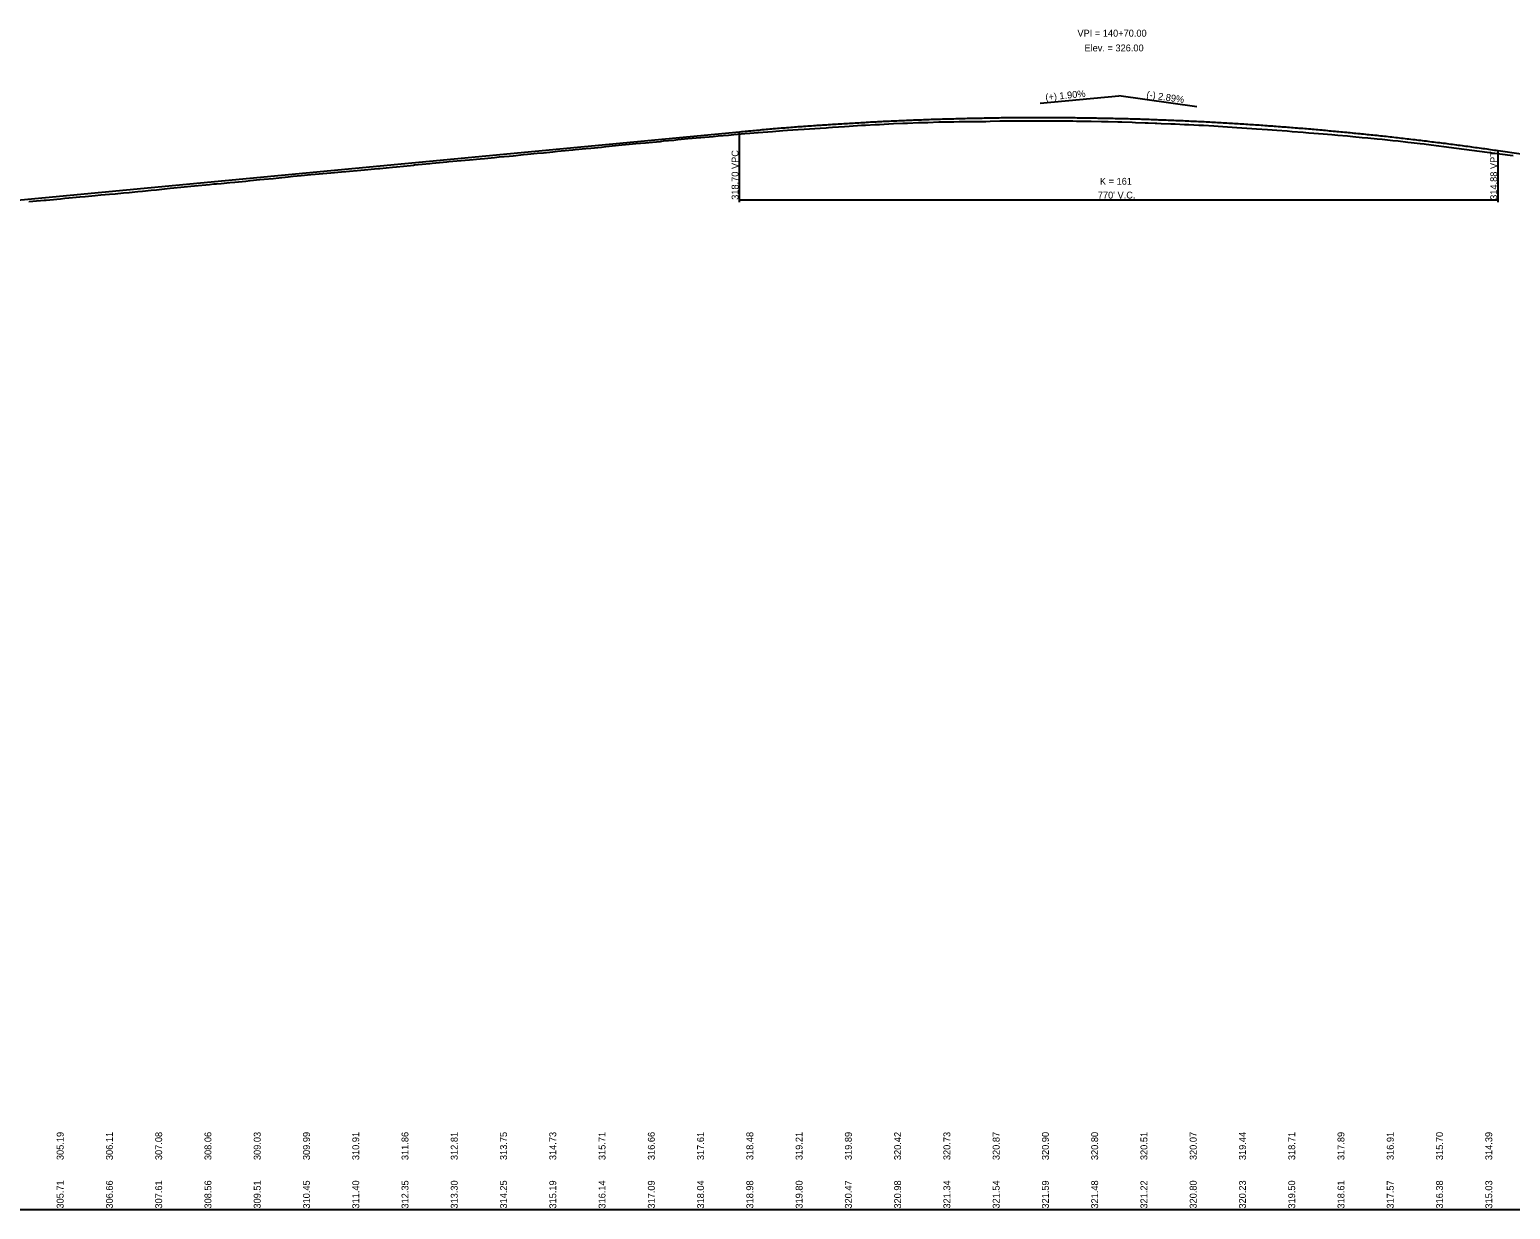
# Model space of a CAD drawing. Extents: x 1876258 to 1926563, y 729739 to 834437.
# Drawn here: x 1891328 to 1892831, y 827963 to 829160 of the extents above; entities that cross this region are included whole.
import ezdxf

# ---------------------------------------------------------------- set-up
doc = ezdxf.new("R2010")
doc.units = 0
for name, color, linetype in [('RD_EX_BldgApp', 7, 'Continuous'), ('RD_EX_H2O_BlueLn', 7, 'Continuous'), ('RD_EX_RailRoad', 7, 'Continuous'), ('RD_HC_Data', 7, 'Continuous'), ('RD_HC_TX_Sta50', 7, 'Continuous'), ('RD_PD_ALT5_CL', 7, 'Continuous'), ('RD_PD_Final_Cl', 7, 'Continuous')]:
    doc.layers.add(name, color=color, linetype=linetype)

msp = doc.modelspace()

# ---------------------------------------------------------------- linework, layer by layer
at = {"layer": 'RD_EX_BldgApp'}
for points in [[(1891683, 829019), (1891695.9, 829020.4), (1891700.1, 829020.8), (1891714.2, 829022.2), (1891717.3, 829022.5), (1891718.2, 829022.6), (1891733.7, 829024.2), (1891736.2, 829024.4), (1891750.9, 829025.8), (1891753.2, 829026), (1891769.6, 829027.4), (1891774.1, 829027.9), (1891784.9, 829028.9), (1891789.2, 829029.3), (1891799.6, 829030.2), (1891804.1, 829030.7), (1891814.2, 829031.6), (1891818.5, 829032), (1891828.9, 829033.1), (1891832.8, 829033.5), (1891842.9, 829034.4), (1891849.1, 829035), (1891858.7, 829036), (1891863.5, 829036.5), (1891874.9, 829037.6), (1891879, 829038), (1891881.3, 829038.2), (1891892.2, 829039.2), (1891897.1, 829039.7), (1891908.1, 829040.8), (1891912.6, 829041.3), (1891922.4, 829042.3), (1891928.7, 829042.9), (1891936.2, 829043.6), (1891942.9, 829044.2), (1891952.6, 829045.2), (1891959.8, 829045.8), (1891967.8, 829046.5), (1891970.9, 829046.9), (1891981.3, 829047.9), (1891985.4, 829048.3), (1891995.5, 829049.3), (1891999.9, 829049.7), (1892004, 829050.1), (1892008.7, 829050.5), (1892021.5, 829051.5), (1892026.5, 829052), (1892036.8, 829052.9), (1892042.2, 829053.4), (1892053.6, 829054.4), (1892058.7, 829054.9), (1892067.1, 829055.6), (1892076.7, 829056.3), (1892081.7, 829056.7), (1892092.2, 829057.4), (1892096.9, 829057.8), (1892107.7, 829058.5), (1892113.6, 829058.9), (1892124.7, 829059.6), (1892129.9, 829060), (1892136.1, 829060.4), (1892138.4, 829060.5), (1892142.6, 829060.9), (1892154.8, 829061.7), (1892159.5, 829062), (1892171.8, 829062.8), (1892175.9, 829063), (1892185.7, 829063.6), (1892190.1, 829063.8), (1892199.8, 829064.3), (1892204.5, 829064.5), (1892214, 829064.9), (1892218.7, 829065.1), (1892229.9, 829065.5), (1892234.5, 829065.6), (1892239.4, 829065.8), (1892250.4, 829066.2), (1892255.5, 829066.3), (1892265.7, 829066.5), (1892270.9, 829066.6), (1892280.8, 829066.7), (1892286.1, 829066.8), (1892298, 829066.8), (1892302.4, 829066.9), (1892312.2, 829067.2), (1892314.3, 829067.2), (1892317.7, 829067.2), (1892326.1, 829067.3), (1892330.8, 829067.4), (1892339.6, 829067.3), (1892344.2, 829067.3), (1892353.6, 829067.4), (1892357.9, 829067.3), (1892368.1, 829067.2), (1892371.7, 829067.2), (1892375.8, 829067.2), (1892386.4, 829067.2), (1892390, 829067.1), (1892401.7, 829067), (1892405.1, 829066.9), (1892415.5, 829066.7)], [(1892415.5, 829066.7), (1892418.6, 829066.7), (1892422.2, 829066.6), (1892432.1, 829066.3), (1892436, 829066.2), (1892446.6, 829065.9), (1892450.2, 829065.8), (1892460, 829065.4), (1892463, 829065.3), (1892470.1, 829065.1), (1892471.8, 829065), (1892476, 829064.8), (1892485.9, 829064.4), (1892490.4, 829064.2), (1892499.7, 829063.8), (1892504.1, 829063.6), (1892514.4, 829063.1), (1892519, 829062.8), (1892529.5, 829062.2), (1892534, 829061.9), (1892543.3, 829061.3), (1892553, 829060.7), (1892558, 829060.4), (1892568, 829059.7), (1892572.7, 829059.4), (1892583.9, 829058.5), (1892588.7, 829058.2), (1892593.5, 829057.8), (1892603.9, 829057.1), (1892609, 829056.7), (1892620.3, 829055.8), (1892622.8, 829055.6), (1892626.1, 829055.3), (1892631.1, 829054.9), (1892640.4, 829054.1), (1892649.2, 829053.4), (1892655.5, 829052.9), (1892665.1, 829052.1), (1892670.6, 829051.6), (1892680.1, 829050.6), (1892685.9, 829050), (1892695.4, 829049.1), (1892700.4, 829048.6), (1892711.3, 829047.5), (1892716.8, 829046.9), (1892726.3, 829045.8), (1892729.8, 829045.5), (1892738.9, 829044.4), (1892742.9, 829043.9), (1892745.1, 829043.6), (1892775.8, 829039.6), (1892830.4, 829032.5), (1892833.4, 829032.1)], [(1891326.9, 828985.4), (1891330.8, 828985.7), (1891342.4, 828986.7), (1891344.4, 828986.9), (1891348.2, 828987.3), (1891358.8, 828988.3), (1891363.2, 828988.8), (1891367.3, 828989.1), (1891378.6, 828990.2), (1891384, 828990.6), (1891394, 828991.5), (1891399.9, 828992.1), (1891408.8, 828992.9), (1891414.3, 828993.4), (1891422.9, 828994.3), (1891428.8, 828994.8), (1891437.3, 828995.6), (1891442.1, 828996.1), (1891451.1, 828997), (1891456.3, 828997.5), (1891467.1, 828998.6), (1891470.2, 828998.9), (1891481.1, 829000), (1891484.3, 829000.3), (1891491.3, 829001), (1891494.9, 829001.3), (1891510, 829002.8), (1891514.7, 829003.3), (1891517.3, 829003.5), (1891522.1, 829003.9), (1891530.8, 829004.7), (1891536, 829005.2), (1891547.2, 829006.3), (1891551.6, 829006.8), (1891561.2, 829007.8), (1891565.6, 829008.2), (1891574.9, 829009), (1891580.6, 829009.5), (1891590.1, 829010.5), (1891595.2, 829011.1), (1891603.3, 829011.9), (1891613.1, 829012.8), (1891617.5, 829013.2), (1891629.3, 829014.3), (1891633.4, 829014.6), (1891644.2, 829015.6), (1891648.7, 829016.1), (1891663.9, 829017.4), (1891667.5, 829017.7), (1891677.5, 829018.6), (1891681, 829018.9), (1891683, 829019)]]:
    msp.add_lwpolyline(points, dxfattribs=at)
at = {"layer": 'RD_EX_H2O_BlueLn'}
for p, q in [((1892048.1, 828984.7), (1892048.1, 829056.3)), ((1892818.1, 828984.7), (1892818.1, 829037.2)), ((1892048.1, 828987.2), (1892818.1, 828987.2))]:
    msp.add_line(p, q, dxfattribs=at)
at = {"layer": 'RD_HC_TX_Sta50'}
for p in [(1892353.4, 829085.3), (1892512.3, 829081.4)]:
    msp.add_line(p, (1892433.1, 829092.8), dxfattribs=at)
at = {"layer": 'RD_PD_ALT5_CL'}
for p, q in [((1889808.1, 828844), (1892048.1, 829056.3)), ((1892818.1, 829037.2), (1894783.1, 828753.6))]:
    msp.add_line(p, q, dxfattribs=at)
msp.add_spline([(1892048.1, 829056.3), (1892063.5, 829057.7), (1892078.9, 829059.1), (1892094.3, 829060.4), (1892109.7, 829061.6), (1892125.1, 829062.7), (1892140.5, 829063.7), (1892155.9, 829064.7), (1892171.3, 829065.6), (1892186.7, 829066.5), (1892202.1, 829067.2), (1892217.5, 829067.9), (1892232.9, 829068.5), (1892248.3, 829069.1), (1892263.7, 829069.5), (1892279.1, 829069.9), (1892294.5, 829070.2), (1892309.9, 829070.5), (1892325.3, 829070.7), (1892340.7, 829070.7), (1892356.1, 829070.8), (1892371.5, 829070.7), (1892386.9, 829070.6), (1892402.3, 829070.4), (1892417.7, 829070.1), (1892433.1, 829069.8), (1892448.5, 829069.4), (1892463.9, 829068.9), (1892479.3, 829068.3), (1892494.7, 829067.7), (1892510.1, 829067), (1892525.5, 829066.2), (1892540.9, 829065.3), (1892556.3, 829064.4), (1892571.7, 829063.4), (1892587.1, 829062.3), (1892602.5, 829061.1), (1892617.9, 829059.9), (1892633.3, 829058.6), (1892648.7, 829057.2), (1892664.1, 829055.8), (1892679.5, 829054.2), (1892694.9, 829052.7), (1892710.3, 829051), (1892725.7, 829049.2), (1892741.1, 829047.4), (1892756.5, 829045.5), (1892771.9, 829043.6), (1892787.3, 829041.5), (1892802.7, 829039.4), (1892818.1, 829037.2)], degree=3, dxfattribs=at)
at = {"layer": 'RD_PD_Final_Cl'}
msp.add_line((1878363.1, 827962.8), (1926563.1, 827962.8), dxfattribs=at)

# ---------------------------------------------------------------- texts
at = {"layer": 'RD_EX_H2O_BlueLn'}
for s, p in [('K = 161', (1892413.9, 829002.5)), ("770' V.C.", (1892411.8, 828988.5))]:
    msp.add_text(s, height=7, dxfattribs=at).set_placement(p)
at = {"layer": 'RD_EX_RailRoad'}
for s, p in [('318.70 VPC', (1892047.1, 828987.2)), ('314.88 VPT', (1892817.1, 828987.2)), ('305.19', (1891362.1, 828012.8)), ('306.11', (1891412.1, 828012.8)), ('307.08', (1891462.1, 828012.8)), ('308.06', (1891512.1, 828012.8)), ('309.03', (1891562.1, 828012.8)), ('309.99', (1891612.1, 828012.8)), ('310.91', (1891662.1, 828012.8)), ('311.86', (1891712.1, 828012.8)), ('312.81', (1891762.1, 828012.8)), ('313.75', (1891812.1, 828012.8)), ('314.73', (1891862.1, 828012.8)), ('315.71', (1891912.1, 828012.8)), ('316.66', (1891962.1, 828012.8)), ('317.61', (1892012.1, 828012.8)), ('318.48', (1892062.1, 828012.8)), ('319.21', (1892112.1, 828012.8)), ('319.89', (1892162.1, 828012.8)), ('320.42', (1892212.1, 828012.8)), ('320.73', (1892262.1, 828012.8)), ('320.87', (1892312.1, 828012.8)), ('320.90', (1892362.1, 828012.8)), ('320.80', (1892412.1, 828012.8)), ('320.51', (1892462.1, 828012.8)), ('320.07', (1892512.1, 828012.8)), ('319.44', (1892562.1, 828012.8)), ('318.71', (1892612.1, 828012.8)), ('317.89', (1892662.1, 828012.8)), ('316.91', (1892712.1, 828012.8)), ('315.70', (1892762.1, 828012.8)), ('314.39', (1892812.1, 828012.8)), ('305.71', (1891362.1, 827963.6)), ('306.66', (1891412.1, 827963.6)), ('307.61', (1891462.1, 827963.6)), ('308.56', (1891512.1, 827963.6)), ('309.51', (1891562.1, 827963.6)), ('310.45', (1891612.1, 827963.6)), ('311.40', (1891662.1, 827963.6)), ('312.35', (1891712.1, 827963.6)), ('313.30', (1891762.1, 827963.6)), ('314.25', (1891812.1, 827963.6)), ('315.19', (1891862.1, 827963.6)), ('316.14', (1891912.1, 827963.6)), ('317.09', (1891962.1, 827963.6)), ('318.04', (1892012.1, 827963.6)), ('318.98', (1892062.1, 827963.6)), ('319.80', (1892112.1, 827963.6)), ('320.47', (1892162.1, 827963.6)), ('320.98', (1892212.1, 827963.6)), ('321.34', (1892262.1, 827963.6)), ('321.54', (1892312.1, 827963.6)), ('321.59', (1892362.1, 827963.6)), ('321.48', (1892412.1, 827963.6)), ('321.22', (1892462.1, 827963.6)), ('320.80', (1892512.1, 827963.6)), ('320.23', (1892562.1, 827963.6)), ('319.50', (1892612.1, 827963.6)), ('318.61', (1892662.1, 827963.6)), ('317.57', (1892712.1, 827963.6)), ('316.38', (1892762.1, 827963.6)), ('315.03', (1892812.1, 827963.6))]:
    msp.add_text(s, height=7, rotation=90, dxfattribs=at).set_placement(p)
at = {"layer": 'RD_HC_Data'}
for s, p in [('VPI = 140+70.00', (1892391.1, 829152.8)), ('Elev. = 326.00', (1892398.2, 829137.8))]:
    msp.add_text(s, height=7, dxfattribs=at).set_placement(p)
at = {"layer": 'RD_HC_TX_Sta50'}
for s, rotation, p in [('(+) 1.90%', 5.4151, (1892358.9, 829087.8)), ('(-) 2.89%', 351.7856, (1892460.8, 829090.8))]:
    msp.add_text(s, height=7, rotation=rotation, dxfattribs=at).set_placement(p)

doc.saveas('drawing.dxf')
